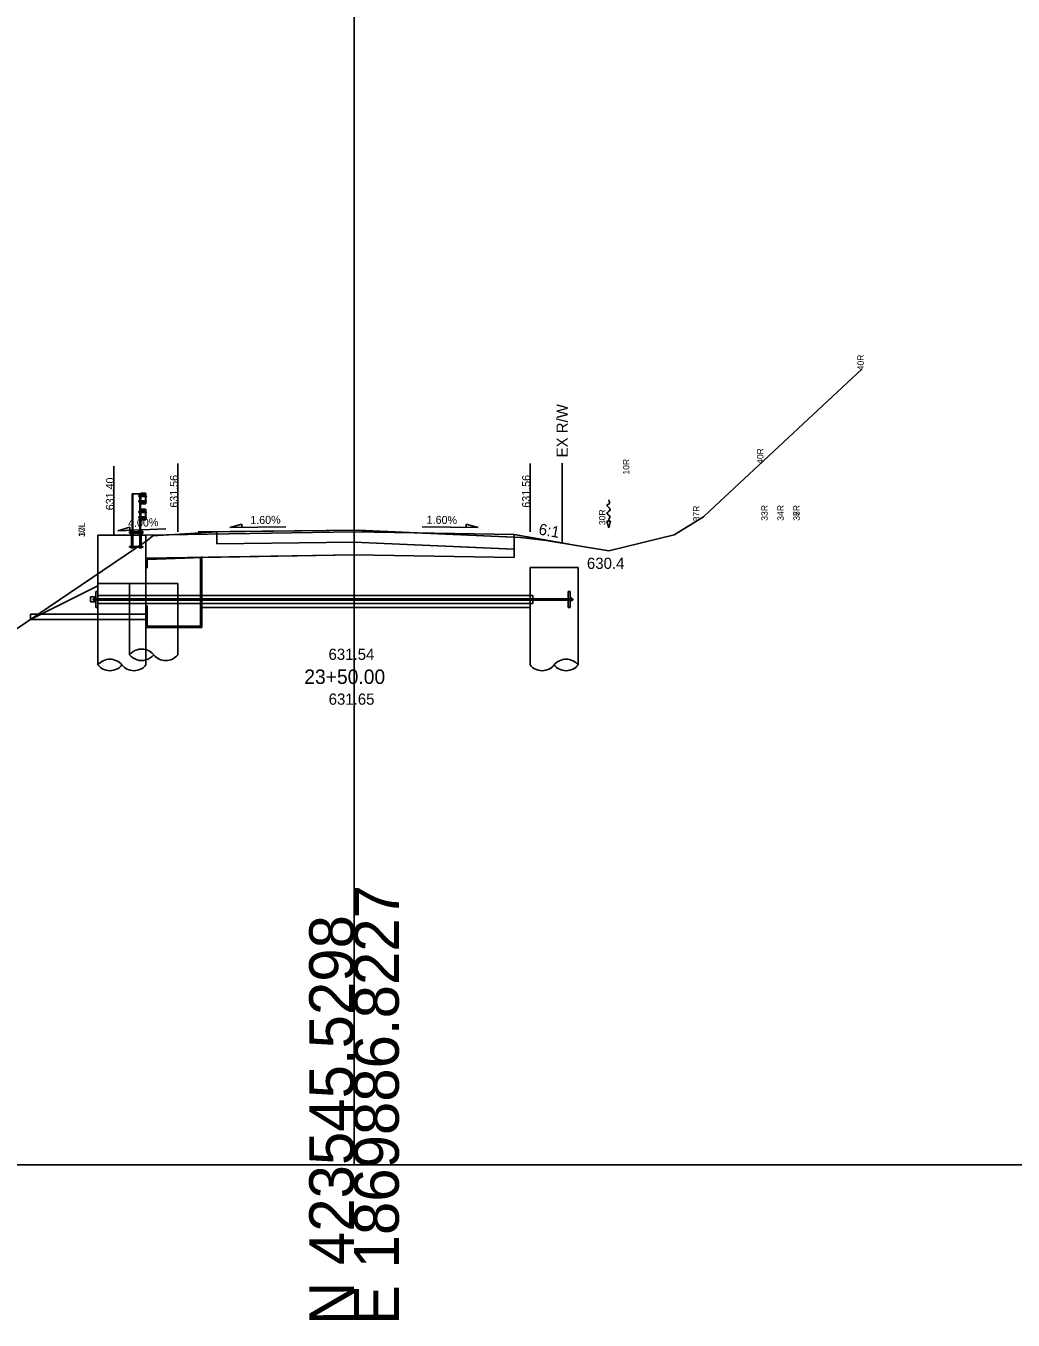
# Model space of a CAD drawing. Extents: x 1866342 to 1870084, y 421982 to 426629.
# Drawn here: x 1866447.6 to 1866509.3, y 423480.9 to 423561.8 of the extents above; entities that cross this region are included whole.
import ezdxf

# ---------------------------------------------------------------- set-up
doc = ezdxf.new("R2010")
doc.units = 0
for name, color, linetype in [('BR_P_Det_Object', 7, 'Continuous'), ('BR_P_Drain_Object', 7, 'Continuous'), ('BR_P_Gen_Hatch', 7, 'Continuous'), ('BR_P_Gen_Porous_Backfill', 7, 'Continuous'), ('BR_P_Sub_Deep_Hidden', 7, 'Continuous'), ('BR_P_Sub_Deep_Object', 7, 'Continuous'), ('BR_P_Sub_Object', 7, 'Continuous'), ('DR_P_Flow_Arrow', 7, 'Continuous'), ('GK_Cells', 7, 'Continuous'), ('RW_X_Fee_RW', 7, 'Continuous'), ('ST_Details', 7, 'Continuous'), ('XS_P_Annotation', 7, 'Continuous'), ('XS_P_Earthwork_Shapes', 7, 'Continuous'), ('XS_P_Finished_Grade', 7, 'Continuous'), ('XS_P_Pavt_Surface', 7, 'Continuous'), ('XS_P_Subgrade', 7, 'Continuous'), ('XS_P_Text_Info', 7, 'Continuous'), ('XS_P_Text_MarkedPoint', 7, 'Continuous'), ('XS_X_Ground_Line', 7, 'Continuous')]:
    doc.layers.add(name, color=color, linetype=linetype)

msp = doc.modelspace()

# ---------------------------------------------------------------- linework, layer by layer
at = {"layer": 'BR_P_Det_Object'}
for p, q in [((1866451.66, 423525.816), (1866451.66, 423526.114)), ((1866451.66, 423526.114), (1866451.994, 423526.114)), ((1866451.994, 423525.466), (1866451.994, 423526.466)), ((1866451.994, 423526.466), (1866452.119, 423526.466)), ((1866452.119, 423526.466), (1866452.119, 423525.466)), ((1866452.119, 423526.216), (1866455.119, 423526.216)), ((1866481.494, 423526.466), (1866481.494, 423525.466)), ((1866481.619, 423526.466), (1866481.494, 423526.466)), ((1866481.619, 423525.466), (1866481.619, 423526.466)), ((1866481.619, 423526.081), (1866481.682, 423526.081)), ((1866481.682, 423525.851), (1866481.682, 423526.081)), ((1866451.994, 423525.816), (1866451.66, 423525.816)), ((1866451.827, 423526.008), (1866481.785, 423526.008)), ((1866451.827, 423525.925), (1866451.827, 423526.008)), ((1866451.827, 423525.925), (1866481.785, 423525.925)), ((1866451.994, 423526.061), (1866451.93, 423526.061)), ((1866451.93, 423525.872), (1866451.93, 423526.061)), ((1866451.994, 423525.872), (1866451.93, 423525.872)), ((1866452.119, 423525.466), (1866451.994, 423525.466)), ((1866452.119, 423525.716), (1866455.119, 423525.716)), ((1866481.619, 423525.466), (1866481.494, 423525.466)), ((1866481.619, 423525.851), (1866481.682, 423525.851)), ((1866481.785, 423525.925), (1866481.785, 423526.008))]:
    msp.add_line(p, q, dxfattribs=at)
at = {"layer": 'BR_P_Drain_Object'}
for p, q in [((1866455.119, 423526.216), (1866479.285, 423526.216)), ((1866479.285, 423526.216), (1866479.285, 423525.716)), ((1866455.119, 423525.716), (1866479.285, 423525.716)), ((1866447.917, 423525.05), (1866455.119, 423525.05)), ((1866447.917, 423524.716), (1866447.917, 423525.05)), ((1866447.917, 423524.716), (1866455.119, 423524.716))]:
    msp.add_line(p, q, dxfattribs=at)
at = {"layer": 'BR_P_Gen_Hatch'}
msp.add_lwpolyline([(1866455.119, 423527.949), (1866455.202, 423527.949), (1866455.202, 423528.449), (1866458.519, 423528.572), (1866458.519, 423524.3), (1866455.202, 423524.3), (1866455.202, 423525.55), (1866455.119, 423525.55)], close=True, dxfattribs=at)
at = {"layer": 'BR_P_Gen_Porous_Backfill'}
for p, q in [((1866455.202, 423528.449), (1866458.119, 423528.566)), ((1866458.519, 423528.572), (1866458.119, 423528.566)), ((1866458.519, 423524.3), (1866458.519, 423528.572)), ((1866455.202, 423527.949), (1866455.119, 423527.949)), ((1866455.202, 423527.949), (1866455.202, 423528.449)), ((1866455.202, 423525.55), (1866455.119, 423525.55)), ((1866455.202, 423524.3), (1866455.202, 423525.55)), ((1866455.202, 423524.3), (1866458.519, 423524.3))]:
    msp.add_line(p, q, dxfattribs=at)
at = {"layer": 'BR_P_Sub_Deep_Hidden'}
msp.add_line((1866457.103, 423526.966), (1866455.119, 423526.966), dxfattribs=at)
for points in [[(1866454.103, 423522.503), (1866454.103, 423526.966)], [(1866457.103, 423524.216), (1866457.103, 423526.966)]]:
    msp.add_lwpolyline(points, dxfattribs=at)
for centre, major_axis, start_param, end_param in [((1866454.853, 423521.9), (0.908, 0.32), 0.952163, 2.125879), ((1866454.853, 423523.106), (0.908, -0.32), 4.157306, 5.331022)]:
    msp.add_ellipse(centre, major_axis=major_axis, ratio=0.999997, start_param=start_param, end_param=end_param, dxfattribs=at)
at = {"layer": 'BR_P_Sub_Deep_Object'}
msp.add_line((1866479.119, 423527.966), (1866482.119, 423527.966), dxfattribs=at)
for points in [[(1866479.119, 423521.87), (1866479.119, 423527.966)], [(1866482.119, 423521.87), (1866482.119, 423527.966)], [(1866452.119, 423521.87), (1866452.119, 423526.966)], [(1866455.119, 423521.87), (1866455.119, 423526.966)], [(1866457.103, 423522.503), (1866457.103, 423524.216)]]:
    msp.add_lwpolyline(points, dxfattribs=at)
for centre, major_axis, start_param, end_param in [((1866452.869, 423521.267), (0.908, 0.32), 0.338571, 2.125879), ((1866454.853, 423521.9), (0.908, 0.32), 0.338571, 0.952163), ((1866454.853, 423523.106), (0.908, -0.32), 5.331022, 5.944615), ((1866456.353, 423523.106), (0.908, 0.32), 3.480163, 5.267472), ((1866481.369, 423521.267), (-0.908, 0.32), 4.157306, 5.944615), ((1866452.869, 423522.473), (0.908, -0.32), 4.157306, 5.944615), ((1866454.369, 423522.473), (0.908, 0.32), 3.480163, 5.267472), ((1866479.869, 423522.473), (-0.908, 0.32), 1.015713, 2.803022), ((1866481.369, 423522.473), (-0.908, -0.32), 0.33857, 2.125879)]:
    msp.add_ellipse(centre, major_axis=major_axis, ratio=0.999997, start_param=start_param, end_param=end_param, dxfattribs=at)
at = {"layer": 'BR_P_Sub_Object'}
for p, q in [((1866455.119, 423529.966), (1866452.119, 423529.966)), ((1866452.119, 423529.966), (1866452.119, 423526.966)), ((1866455.119, 423526.966), (1866455.119, 423529.966))]:
    msp.add_line(p, q, dxfattribs=at)
msp.add_lwpolyline([(1866455.119, 423526.966), (1866452.119, 423526.966)], dxfattribs=at)
at = {"layer": 'DR_P_Flow_Arrow'}
for p, q in [((1866484.027, 423530.44), (1866483.92, 423530.84)), ((1866483.92, 423530.84), (1866484.134, 423530.84)), ((1866484.134, 423530.84), (1866484.027, 423530.44))]:
    msp.add_line(p, q, dxfattribs=at)
msp.add_spline([(1866484.028, 423530.84), (1866484.028, 423530.856), (1866484.066, 423531.02), (1866484.102, 423531.125), (1866483.918, 423531.337), (1866484.124, 423531.579), (1866483.918, 423531.859), (1866484.03, 423531.916), (1866484.027, 423532.19)], degree=3, dxfattribs=at)
at = {"layer": 'GK_Cells'}
for p, q in [((1866468.119, 423490.634), (1866468.119, 423639.795)), ((1866368.119, 423490.634), (1866468.119, 423490.634)), ((1866468.119, 423490.634), (1866568.119, 423490.634))]:
    msp.add_line(p, q, dxfattribs=at)
at = {"layer": 'RW_X_Fee_RW'}
msp.add_line((1866481.119, 423529.483), (1866481.119, 423534.483), dxfattribs=at)
at = {"layer": 'ST_Details'}
for p, q in [((1866454.254, 423532.55), (1866454.254, 423530.331)), ((1866454.785, 423532.55), (1866454.254, 423532.55)), ((1866454.292, 423532.55), (1866454.292, 423530.325)), ((1866454.747, 423532.55), (1866454.747, 423530.325)), ((1866454.785, 423532.55), (1866454.785, 423530.331)), ((1866455.067, 423532.591), (1866454.837, 423532.591)), ((1866455.067, 423532.565), (1866454.837, 423532.565)), ((1866454.701, 423532.451), (1866454.685, 423532.451)), ((1866454.685, 423532.451), (1866454.685, 423532.399)), ((1866454.701, 423532.399), (1866454.685, 423532.399)), ((1866454.701, 423532.117), (1866454.685, 423532.117)), ((1866454.685, 423532.117), (1866454.685, 423532.065)), ((1866454.701, 423532.065), (1866454.685, 423532.065)), ((1866454.701, 423532.458), (1866454.701, 423532.391)), ((1866454.701, 423532.125), (1866454.701, 423532.058)), ((1866454.71, 423532.403), (1866454.747, 423532.403)), ((1866454.71, 423532.069), (1866454.747, 423532.069)), ((1866454.747, 423532.469), (1866454.711, 423532.469)), ((1866454.711, 423532.447), (1866454.747, 423532.447)), ((1866454.711, 423532.38), (1866454.747, 423532.38)), ((1866454.747, 423532.136), (1866454.711, 423532.136)), ((1866454.711, 423532.113), (1866454.747, 423532.113)), ((1866454.711, 423532.047), (1866454.747, 423532.047)), ((1866454.747, 423532.38), (1866454.747, 423532.469)), ((1866454.747, 423532.047), (1866454.747, 423532.136)), ((1866454.785, 423532.539), (1866454.785, 423531.977)), ((1866454.811, 423532.539), (1866454.811, 423531.977)), ((1866454.811, 423532.451), (1866455.093, 423532.451)), ((1866454.811, 423532.399), (1866455.093, 423532.399)), ((1866454.811, 423532.117), (1866455.093, 423532.117)), ((1866454.811, 423532.065), (1866455.093, 423532.065)), ((1866454.837, 423531.951), (1866455.067, 423531.951)), ((1866454.837, 423531.925), (1866455.067, 423531.925)), ((1866455.093, 423531.977), (1866455.093, 423532.539)), ((1866455.119, 423531.977), (1866455.119, 423532.539)), ((1866454.701, 423531.451), (1866454.685, 423531.451)), ((1866454.685, 423531.451), (1866454.685, 423531.399)), ((1866454.701, 423531.399), (1866454.685, 423531.399)), ((1866454.701, 423531.117), (1866454.685, 423531.117)), ((1866454.685, 423531.117), (1866454.685, 423531.065)), ((1866454.701, 423531.065), (1866454.685, 423531.065)), ((1866454.701, 423531.458), (1866454.701, 423531.391)), ((1866454.701, 423531.125), (1866454.701, 423531.058)), ((1866454.71, 423531.403), (1866454.747, 423531.403)), ((1866454.71, 423531.069), (1866454.747, 423531.069)), ((1866454.747, 423531.469), (1866454.711, 423531.469)), ((1866454.711, 423531.447), (1866454.747, 423531.447)), ((1866454.711, 423531.38), (1866454.747, 423531.38)), ((1866454.747, 423531.136), (1866454.711, 423531.136)), ((1866454.711, 423531.113), (1866454.747, 423531.113)), ((1866454.711, 423531.047), (1866454.747, 423531.047)), ((1866454.747, 423531.38), (1866454.747, 423531.469)), ((1866454.747, 423531.047), (1866454.747, 423531.136)), ((1866454.785, 423531.56), (1866454.785, 423530.956)), ((1866454.811, 423531.539), (1866454.811, 423530.977)), ((1866454.811, 423531.451), (1866455.093, 423531.451)), ((1866454.811, 423531.399), (1866455.093, 423531.399)), ((1866454.811, 423531.117), (1866455.093, 423531.117)), ((1866454.811, 423531.065), (1866455.093, 423531.065)), ((1866455.087, 423531.591), (1866454.817, 423531.591)), ((1866455.067, 423531.565), (1866454.837, 423531.565)), ((1866454.837, 423530.951), (1866455.067, 423530.951)), ((1866455.093, 423530.977), (1866455.093, 423531.539)), ((1866455.119, 423530.956), (1866455.119, 423531.56)), ((1866454.171, 423530.2), (1866454.337, 423530.2)), ((1866454.171, 423530.185), (1866454.171, 423530.2)), ((1866454.337, 423530.185), (1866454.171, 423530.185)), ((1866454.176, 423530.266), (1866454.176, 423530.2)), ((1866454.332, 423530.2), (1866454.176, 423530.2)), ((1866454.195, 423530.282), (1866454.312, 423530.282)), ((1866454.212, 423530.321), (1866454.223, 423530.331)), ((1866454.212, 423530.321), (1866454.296, 423530.321)), ((1866454.212, 423530.321), (1866454.212, 423530.282)), ((1866454.212, 423530.31), (1866454.296, 423530.31)), ((1866454.212, 423530.3), (1866454.296, 423530.3)), ((1866454.212, 423530.29), (1866454.296, 423530.29)), ((1866454.212, 423530.185), (1866454.212, 423530.102)), ((1866454.215, 423530.266), (1866454.215, 423530.2)), ((1866454.285, 423530.331), (1866454.223, 423530.331)), ((1866454.285, 423530.331), (1866454.296, 423530.321)), ((1866454.293, 423530.266), (1866454.293, 423530.2)), ((1866454.296, 423530.282), (1866454.296, 423530.321)), ((1866454.296, 423530.102), (1866454.296, 423530.185)), ((1866454.332, 423530.266), (1866454.332, 423530.2)), ((1866454.337, 423530.2), (1866454.337, 423530.185)), ((1866454.868, 423530.2), (1866454.702, 423530.2)), ((1866454.702, 423530.2), (1866454.702, 423530.185)), ((1866454.702, 423530.185), (1866454.868, 423530.185)), ((1866454.707, 423530.266), (1866454.707, 423530.2)), ((1866454.707, 423530.2), (1866454.863, 423530.2)), ((1866454.844, 423530.282), (1866454.726, 423530.282)), ((1866454.754, 423530.331), (1866454.743, 423530.321)), ((1866454.827, 423530.321), (1866454.743, 423530.321)), ((1866454.743, 423530.282), (1866454.743, 423530.321)), ((1866454.827, 423530.31), (1866454.743, 423530.31)), ((1866454.827, 423530.3), (1866454.743, 423530.3)), ((1866454.827, 423530.29), (1866454.743, 423530.29)), ((1866454.743, 423530.102), (1866454.743, 423530.185)), ((1866454.746, 423530.266), (1866454.746, 423530.2)), ((1866454.754, 423530.331), (1866454.816, 423530.331)), ((1866454.827, 423530.321), (1866454.816, 423530.331)), ((1866454.817, 423530.925), (1866455.087, 423530.925)), ((1866454.824, 423530.266), (1866454.824, 423530.2)), ((1866454.827, 423530.321), (1866454.827, 423530.282)), ((1866454.827, 423530.185), (1866454.827, 423530.102)), ((1866454.863, 423530.266), (1866454.863, 423530.2)), ((1866454.868, 423530.185), (1866454.868, 423530.2)), ((1866454.171, 423530.102), (1866454.337, 423530.102)), ((1866454.171, 423530.087), (1866454.171, 423530.102)), ((1866454.337, 423530.087), (1866454.171, 423530.087)), ((1866454.176, 423530.057), (1866454.176, 423530.087)), ((1866454.195, 423530.042), (1866454.312, 423530.042)), ((1866454.212, 423529.977), (1866454.212, 423530.042)), ((1866454.212, 423529.977), (1866454.212, 423529.258)), ((1866454.215, 423530.057), (1866454.215, 423530.087)), ((1866454.293, 423530.057), (1866454.293, 423530.087)), ((1866454.296, 423529.977), (1866454.296, 423530.042)), ((1866454.296, 423529.258), (1866454.296, 423529.977)), ((1866454.332, 423530.057), (1866454.332, 423530.087)), ((1866454.337, 423530.102), (1866454.337, 423530.087)), ((1866454.702, 423530.102), (1866454.868, 423530.102)), ((1866454.702, 423530.087), (1866454.702, 423530.102)), ((1866454.868, 423530.087), (1866454.702, 423530.087)), ((1866454.707, 423530.057), (1866454.707, 423530.087)), ((1866454.726, 423530.042), (1866454.844, 423530.042)), ((1866454.743, 423529.977), (1866454.743, 423530.042)), ((1866454.743, 423529.258), (1866454.743, 423529.977)), ((1866454.746, 423530.057), (1866454.746, 423530.087)), ((1866454.824, 423530.057), (1866454.824, 423530.087)), ((1866454.827, 423529.977), (1866454.827, 423530.042)), ((1866454.827, 423529.977), (1866454.827, 423529.258)), ((1866454.863, 423530.057), (1866454.863, 423530.087)), ((1866454.868, 423530.102), (1866454.868, 423530.087)), ((1866454.176, 423529.192), (1866454.176, 423529.227)), ((1866454.195, 423529.176), (1866454.312, 423529.176)), ((1866454.215, 423529.192), (1866454.215, 423529.227)), ((1866454.293, 423529.192), (1866454.293, 423529.227)), ((1866454.332, 423529.192), (1866454.332, 423529.227)), ((1866454.707, 423529.192), (1866454.707, 423529.227)), ((1866454.844, 423529.176), (1866454.726, 423529.176)), ((1866454.746, 423529.192), (1866454.746, 423529.227)), ((1866454.824, 423529.192), (1866454.824, 423529.227)), ((1866454.863, 423529.192), (1866454.863, 423529.227))]:
    msp.add_line(p, q, dxfattribs=at)
for points in [[(1866454.103, 423530.185), (1866454.936, 423530.185), (1866454.936, 423530.102), (1866454.103, 423530.102)], [(1866454.103, 423529.258), (1866454.936, 423529.258), (1866454.936, 423529.227), (1866454.103, 423529.227)]]:
    msp.add_lwpolyline(points, close=True, dxfattribs=at)
for centre, radius, start, end in [((1866454.837, 423532.539), 0.0521, 90, 180), ((1866454.837, 423532.539), 0.026, 90, 180), ((1866455.067, 423532.539), 0.0521, 0, 90), ((1866455.067, 423532.539), 0.026, 0, 90), ((1866454.837, 423531.977), 0.0521, 180, 270), ((1866454.837, 423531.977), 0.026, 180, 270), ((1866455.067, 423531.977), 0.0521, 270, 0), ((1866455.067, 423531.977), 0.026, 270, 0), ((1866455.091, 423532.425), 0.0558, 300, 60), ((1866455.091, 423532.091), 0.0558, 300, 60), ((1866454.817, 423531.56), 0.0312, 90, 180), ((1866454.817, 423530.956), 0.0312, 180, 270), ((1866454.837, 423531.539), 0.026, 90, 180), ((1866454.837, 423530.977), 0.026, 180, 270), ((1866455.067, 423531.539), 0.026, 0, 90), ((1866455.067, 423530.977), 0.026, 270, 0), ((1866455.087, 423531.56), 0.0312, 0, 90), ((1866455.087, 423530.956), 0.0312, 270, 0), ((1866455.091, 423531.425), 0.0558, 300, 60), ((1866455.091, 423531.091), 0.0558, 300, 60)]:
    msp.add_arc(centre, radius, start, end, dxfattribs=at)
for centre, major_axis, ratio, start_param, end_param in [((1866454.711, 423532.458), (0, -0.0111), 0.939759, 3.141593, 6.283185), ((1866454.711, 423532.425), (0, -0.0222), 0.469173, 3.141593, 6.283185), ((1866454.711, 423532.391), (0, 0.0111), 0.939759, 0, 3.141593), ((1866454.711, 423532.125), (0, -0.0111), 0.939759, 3.141593, 6.283185), ((1866454.711, 423532.091), (0, -0.0222), 0.469173, 3.141593, 6.283185), ((1866454.711, 423532.058), (0, 0.0111), 0.939759, 0, 3.141593), ((1866454.711, 423531.458), (0, -0.0111), 0.939759, 3.141593, 6.283185), ((1866454.711, 423531.425), (0, -0.0222), 0.469173, 3.141593, 6.283185), ((1866454.711, 423531.391), (0, 0.0111), 0.939759, 0, 3.141593), ((1866454.711, 423531.125), (0, -0.0111), 0.939759, 3.141593, 6.283185), ((1866454.711, 423531.091), (0, -0.0222), 0.469173, 3.141593, 6.283185), ((1866454.711, 423531.058), (0, 0.0111), 0.939759, 0, 3.141593), ((1866454.195, 423530.266), (0.0195, 0), 0.798056, 0, 3.141593), ((1866454.254, 423530.266), (0.0391, 0), 0.399304, 0, 3.141593), ((1866454.312, 423530.266), (0.0195, 0), 0.798056, 0, 3.141593), ((1866454.726, 423530.266), (-0.0195, 0), 0.798056, 3.141593, 6.283185), ((1866454.785, 423530.266), (-0.0391, 0), 0.399304, 3.141593, 6.283185), ((1866454.844, 423530.266), (-0.0195, 0), 0.798056, 3.141593, 6.283185), ((1866454.195, 423530.057), (0.0195, 0), 0.798056, 3.141593, 6.283185), ((1866454.254, 423530.057), (0.0391, 0), 0.399304, 3.141593, 6.283185), ((1866454.312, 423530.057), (0.0195, 0), 0.798056, 3.141593, 6.283185), ((1866454.726, 423530.057), (0.0195, 0), 0.798056, 3.141593, 6.283185), ((1866454.785, 423530.057), (0.0391, 0), 0.399304, 3.141593, 6.283185), ((1866454.844, 423530.057), (0.0195, 0), 0.798056, 3.141593, 6.283185), ((1866454.195, 423529.192), (0.0195, 0), 0.798056, 3.141593, 6.283185), ((1866454.254, 423529.192), (0.0391, 0), 0.399304, 3.141593, 6.283185), ((1866454.312, 423529.192), (0.0195, 0), 0.798056, 3.141593, 6.283185), ((1866454.726, 423529.192), (-0.0195, 0), 0.798056, 0, 3.141593), ((1866454.785, 423529.192), (-0.0391, 0), 0.399304, 0, 3.141593), ((1866454.844, 423529.192), (-0.0195, 0), 0.798056, 0, 3.141593)]:
    msp.add_ellipse(centre, major_axis=major_axis, ratio=ratio, start_param=start_param, end_param=end_param, dxfattribs=at)
at = {"layer": 'XS_P_Annotation'}
for q in [(1866455.119, 423529.966), (1866478.119, 423530.014)]:
    msp.add_line((1866468.119, 423530.174), q, dxfattribs=at)
at = {"layer": 'XS_P_Earthwork_Shapes'}
for p, q in [((1866455.119, 423529.58), (1866455.119, 423528.529)), ((1866481.548, 423529.407), (1866478.119, 423530.014)), ((1866478.119, 423530.014), (1866478.119, 423529.845)), ((1866478.119, 423529.845), (1866478.537, 423529.826)), ((1866468.119, 423528.737), (1866478.119, 423528.577)), ((1866478.119, 423528.577), (1866478.119, 423529.095))]:
    msp.add_line(p, q, dxfattribs=at)
for points in [[(1866478.119, 423529.095), (1866468.106, 423529.538), (1866459.553, 423529.444), (1866459.545, 423530.194), (1866455.552, 423529.941), (1866455.202, 423529.636), (1866455.119, 423529.58)], [(1866459.545, 423530.194), (1866468.119, 423530.288), (1866478.119, 423529.845)], [(1866459.553, 423529.444), (1866468.106, 423529.538), (1866478.085, 423529.096)], [(1866478.537, 423529.826), (1866480.112, 423529.645), (1866481.548, 423529.407)], [(1866455.119, 423528.529), (1866458.603, 423528.585), (1866468.119, 423528.737)]]:
    msp.add_lwpolyline(points, dxfattribs=at)
at = {"layer": 'XS_P_Finished_Grade'}
for p, q in [((1866478.119, 423530.014), (1866481.548, 423529.407)), ((1866447.917, 423524.716), (1866452.119, 423526.817))]:
    msp.add_line(p, q, dxfattribs=at)
at = {"layer": 'XS_P_Pavt_Surface'}
for p in [(1866458.373, 423530.182), (1866478.525, 423529.827)]:
    msp.add_line(p, (1866468.373, 423530.291), dxfattribs=at)
at = {"layer": 'XS_P_Subgrade'}
for p, q in [((1866455.119, 423529.966), (1866455.119, 423528.529)), ((1866455.119, 423529.966), (1866455.119, 423528.529)), ((1866478.119, 423530.014), (1866478.119, 423528.577)), ((1866468.119, 423528.737), (1866455.119, 423528.529)), ((1866458.603, 423524.216), (1866458.603, 423528.649)), ((1866468.119, 423528.737), (1866478.119, 423528.577)), ((1866458.603, 423525.466), (1866479.119, 423525.466)), ((1866455.119, 423524.216), (1866458.603, 423524.216))]:
    msp.add_line(p, q, dxfattribs=at)
at = {"layer": 'XS_P_Text_Info'}
for p, q in [((1866453.119, 423530.032), (1866453.119, 423534.282)), ((1866457.119, 423530.192), (1866457.119, 423534.442)), ((1866479.119, 423530.192), (1866479.119, 423534.442)), ((1866454.119, 423530.472), (1866453.369, 423530.242)), ((1866456.369, 423530.362), (1866453.369, 423530.242)), ((1866454.119, 423530.272), (1866454.119, 423530.472)), ((1866461.119, 423530.656), (1866460.369, 423530.444)), ((1866463.869, 423530.5), (1866460.369, 423530.444)), ((1866461.119, 423530.456), (1866461.119, 423530.656)), ((1866472.369, 423530.5), (1866475.869, 423530.444)), ((1866475.119, 423530.656), (1866475.869, 423530.444)), ((1866475.119, 423530.456), (1866475.119, 423530.656))]:
    msp.add_line(p, q, dxfattribs=at)
at = {"layer": 'XS_X_Ground_Line'}
msp.add_line((1866452.119, 423529.966), (1866452.119, 423527.966), dxfattribs=at)
msp.add_lwpolyline([(1866392.147, 423492.144), (1866393.343, 423492.098), (1866396.955, 423491.937), (1866406.629, 423497.065), (1866421.61, 423506.974), (1866427.616, 423511.427), (1866429.18, 423512.433), (1866430.944, 423513.633), (1866431.908, 423513.906), (1866433.498, 423514.826), (1866437.259, 423517.335), (1866437.327, 423517.564), (1866455.202, 423529.636), (1866455.552, 423529.941), (1866459.545, 423530.194), (1866468.373, 423530.291), (1866473.437, 423530.06), (1866478.537, 423529.826), (1866480.112, 423529.645), (1866484.031, 423528.995), (1866488.127, 423529.997), (1866489.95, 423531.121), (1866490.34, 423531.486), (1866499.847, 423540.355)], dxfattribs=at)

# ---------------------------------------------------------------- texts
at = {"layer": 'GK_Cells'}
for s, p in [('E 1869886.8227', (1866470.919, 423480.634)), ('N 423545.5298', (1866468.119, 423480.634))]:
    msp.add_text(s, height=2.8, rotation=90, dxfattribs=at).set_placement(p)
at = {"layer": 'RW_X_Fee_RW'}
msp.add_text('EX R/W', height=0.7, rotation=90, dxfattribs=at).set_placement((1866481.469, 423534.833))
at = {"layer": 'XS_P_Annotation'}
msp.add_text('6:1', height=0.7, rotation=349.95478, dxfattribs=at).set_placement((1866479.612, 423530.025))
for s, height, p in [('630.4', 0.7, (1866482.667, 423527.868)), ('631.54', 0.7, (1866466.526, 423522.184)), ('23+50.00', 0.9, (1866465.011, 423520.684)), ('631.65', 0.7, (1866466.534, 423519.384))]:
    msp.add_text(s, height=height, dxfattribs=at).set_placement(p)
at = {"layer": 'XS_P_Text_Info'}
for s, rotation, p in [('631.40', 90, (1866453.119, 423531.532)), ('631.56', 90, (1866457.119, 423531.692)), ('631.56', 90, (1866479.119, 423531.692)), ('4.00%', 2.29061, (1866454.013, 423530.468)), ('1.60%', 0.91409, (1866461.642, 423530.664)), ('1.60%', 359.08335, (1866472.655, 423530.695))]:
    msp.add_text(s, height=0.5, rotation=rotation, dxfattribs=at).set_placement(p)
at = {"layer": 'XS_P_Text_MarkedPoint'}
for s, p in [('40R', (1866499.96, 423540.274)), ('40R', (1866493.694, 423534.428)), ('10R', (1866485.319, 423533.758)), ('37R', (1866489.694, 423530.84)), ('33R', (1866493.96, 423530.878)), ('34R', (1866494.96, 423530.878)), ('35R', (1866495.96, 423530.878)), ('36R', (1866495.96, 423530.878)), ('37R', (1866495.96, 423530.878)), ('30R', (1866483.819, 423530.605)), ('10L', (1866451.319, 423529.872)), ('37L', (1866451.319, 423529.872))]:
    msp.add_text(s, height=0.4, rotation=90, dxfattribs=at).set_placement(p)

doc.saveas('drawing.dxf')
